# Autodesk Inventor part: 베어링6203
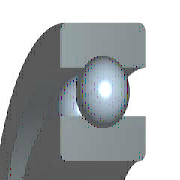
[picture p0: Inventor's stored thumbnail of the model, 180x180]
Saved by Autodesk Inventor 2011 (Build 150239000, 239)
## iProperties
IsCustomPart: 0
Company: 한국ATC센터
Created: 2014-12
Part Number: 베어링6203
Material: 강, 연강
Description: 깊은 그루브 볼 베어링
Document SubType Name: Modeling
Standard: KS B 2023
Designer: KYOUNG IL JANG
Standards Organization: KS
Language: ko-KR
Size Designation: 6203 - 17 x 40 x 12
Categories: <MemberInstance><Categories><Category DisplayName="샤프트 부품" InternalName="7f7aeb1f-a693-4053-b835-cee3144e0d98" Mnemonic="SHFT"><Category DisplayName="베어링" Inter
Density: 7.86 g/cm^3
Mass: 64.9809 g
Surface Area: 64.3582 cm^2
Volume: 8.26729 cm^3
Author: KYOUNG IL JANG
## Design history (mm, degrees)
revolve "본체" stored, may be unused: angle "d6" = 90 deg
revolve "볼" stored, may be unused: angle "d7" = 90 deg
pattern_circular "IDS_ARRAYBALL[SIMPL:T]" dims angle "d3" = 360 deg
body "Solid1"
sketch "스케치" dims "d0" = 5.98 (= -0.26 x WD + 0.26 x BD)
  geometry: L1 (3.01, 14.25)-(8.99, 14.25); L2 (6, 14.25)-(6, 11.26); L3 (6, 14.25)-(6, 17.24); L4 (3.778, 12.249)-(0, 12.249); L5 (0, 8.5)-(12, 8.5); L6 (3.778, 16.251)-(0, 16.251); L7 (0, 20)-(12, 20); L8 (12, 8.5)-(12, 12.249); L9 (8.222, 12.249)-(12, 12.249); L10 (8.222, 16.251)-(12, 16.251); L11 (12, 20)-(12, 16.251); L12 (-1.4, 0)-(8.4, 0) reference; L13 (0, -0.3)-(0, 5.3) reference
  constraints: 22 end point, 4 point on line, 2 collinear, 2 perpendicular, 2 symmetric about line, 1 midpoint, 1 parallel, 14 other
  dimensions: "d9" = 17 diameter of L5 L12 (= WD); "d11" = 40 diameter of L7 L12 (= BD); "d12" = 12 distance between parallel lines of L8 L13 (= KB); "d13" = 24.498 diameter of L9 L12 (= 0.326 x BD + 0.674 x WD)
fillet "모깎기1" dims "d1" = 0.6 (= KRS)
other parameters: "WD" = 17 [user parameter; used in 5 equation terms], "BD" = 40 [user parameter; used in 5 equation terms], "KB" = 12 [user parameter; used in 1 equation term], "KRS" = 0.6 [user parameter; used in 1 equation term], "d4" = 0, "d5" = 0, "d8" = 0, "d14" = 0, "d15" = 0, "BBA" = 0 [user parameter], "BC0" = 4750000 [user parameter], "BC" = 9560000 [user parameter], "WR" = 8.5 (= 0.5 x WD) [user parameter]
